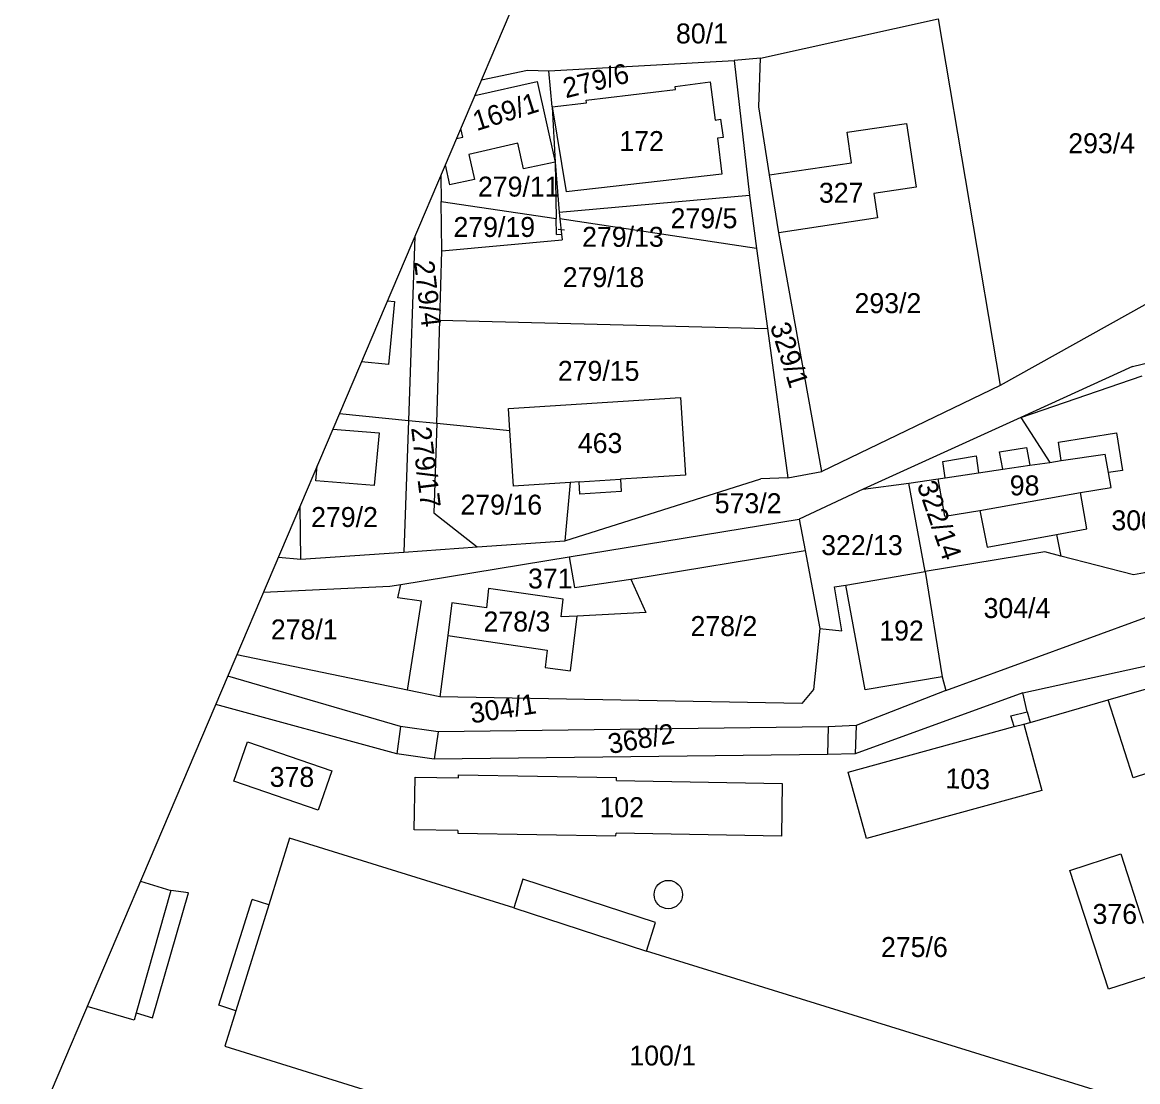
# Model space of a CAD drawing. Extents: x -805826 to -803822, y -1165880 to -1164382.
# Drawn here: x -805826.1 to -805636, y -1165156 to -1164975.4 of the extents above; entities that cross this region are included whole.
import ezdxf

# ---------------------------------------------------------------- set-up
doc = ezdxf.new("R2010")
doc.units = 0
for name, color, linetype in [('formát', 7, 'Continuous'), ('kn_celek - Cisla parcel pomocna', 7, 'Continuous'), ('kn_celek - Cisla pozemkovych parcel', 7, 'Continuous'), ('kn_celek - Cisla stavebnich parcel', 7, 'Continuous'), ('kn_celek - Hranice parcel', 7, 'Continuous'), ('kn_celek - Vnitrni kresby', 7, 'Continuous')]:
    doc.layers.add(name, color=color, linetype=linetype)

msp = doc.modelspace()

# ---------------------------------------------------------------- linework, layer by layer
at = {"layer": 'formát'}
msp.add_line((-805491.17, -1164382.07), (-805826.05, -1165169.15), dxfattribs=at)
at = {"layer": 'kn_celek - Cisla parcel pomocna'}
msp.add_line((-805734.72, -1165010.67), (-805733.68, -1165010.82), dxfattribs=at)
at = {"layer": 'kn_celek - Hranice parcel'}
for p, q in [((-805700.29, -1164981.54), (-805670.01, -1164974.84)), ((-805670.01, -1164974.84), (-805659.45, -1165037.34)), ((-805736.31, -1164983.71), (-805704.74, -1164981.97)), ((-805700.29, -1164981.54), (-805704.74, -1164981.97)), ((-805704.74, -1164981.97), (-805702.16, -1165004.93)), ((-805700.55, -1164989.86), (-805700.29, -1164981.54)), ((-805747.81, -1164985.25), (-805739.97, -1164983.61)), ((-805739.97, -1164983.61), (-805736.31, -1164983.71)), ((-805735.79, -1164989.87), (-805736.31, -1164983.71)), ((-805714.82, -1164986.37), (-805708.85, -1164985.57)), ((-805708.85, -1164985.57), (-805708.01, -1164992.11)), ((-805729.96, -1164988.69), (-805714.77, -1164986.9)), ((-805714.77, -1164986.9), (-805714.82, -1164986.37)), ((-805735.79, -1164989.87), (-805729.91, -1164989.17)), ((-805735.79, -1164989.87), (-805735.26, -1164999.29)), ((-805735.79, -1164989.87), (-805733.38, -1165004.33)), ((-805729.91, -1164989.17), (-805729.96, -1164988.69)), ((-805698.74, -1165001.45), (-805700.55, -1164989.86)), ((-805708.01, -1164992.11), (-805707.08, -1164991.97)), ((-805707.08, -1164991.97), (-805706.65, -1164995.08)), ((-805750.99, -1164995.04), (-805751.33, -1164993.54)), ((-805685.51, -1164994.16), (-805675.37, -1164992.66)), ((-805675.37, -1164992.66), (-805673.76, -1165003.53)), ((-805752.07, -1164995.27), (-805750.99, -1164995.04)), ((-805706.65, -1164995.08), (-805707.62, -1164995.21)), ((-805707.62, -1164995.21), (-805706.85, -1165001.33)), ((-805684.74, -1164999.37), (-805685.51, -1164994.16)), ((-805741.61, -1164996.06), (-805749.94, -1164997.96)), ((-805740.65, -1165000.43), (-805741.61, -1164996.06)), ((-805749.94, -1164997.96), (-805749.02, -1165002.22)), ((-805735.26, -1164999.29), (-805740.65, -1165000.43)), ((-805735.26, -1164999.29), (-805734.57, -1165007.88)), ((-805735.26, -1164999.29), (-805735.06, -1165008.87)), ((-805698.74, -1165001.45), (-805684.74, -1164999.37)), ((-805753.98, -1164999.75), (-805753.25, -1165003.12)), ((-805706.85, -1165001.33), (-805733.38, -1165004.33)), ((-805697.14, -1165011.3), (-805698.74, -1165001.45)), ((-805754.74, -1165001.55), (-805754.68, -1165005.95)), ((-805749.02, -1165002.22), (-805753.25, -1165003.12)), ((-805702.16, -1165004.93), (-805734.57, -1165007.88)), ((-805702.16, -1165004.93), (-805700.92, -1165013.97)), ((-805673.76, -1165003.53), (-805680.97, -1165004.6)), ((-805680.97, -1165004.6), (-805680.35, -1165008.76)), ((-805754.68, -1165005.95), (-805735.06, -1165008.87)), ((-805754.57, -1165014.37), (-805754.68, -1165005.95)), ((-805735, -1165011.63), (-805735.06, -1165008.87)), ((-805734.57, -1165007.88), (-805734.46, -1165008.95)), ((-805700.92, -1165013.97), (-805734.46, -1165008.95)), ((-805734.46, -1165008.95), (-805734.2, -1165011.52)), ((-805680.35, -1165008.76), (-805697.14, -1165011.3)), ((-805759.16, -1165011.94), (-805760.25, -1165043.29)), ((-805754.57, -1165014.37), (-805734.07, -1165012.52)), ((-805735, -1165011.63), (-805734.2, -1165011.52)), ((-805734.2, -1165011.52), (-805734.07, -1165012.52)), ((-805689.79, -1165051.98), (-805697.14, -1165011.3)), ((-805754.9, -1165026.2), (-805754.57, -1165014.37)), ((-805700.92, -1165013.97), (-805699.06, -1165027.61)), ((-805763.83, -1165022.92), (-805762.62, -1165023.04)), ((-805762.62, -1165023.04), (-805763.68, -1165033.73)), ((-805634.8, -1165023.61), (-805659.45, -1165037.34)), ((-805755.4, -1165043.76), (-805754.9, -1165026.2)), ((-805754.9, -1165026.2), (-805699.06, -1165027.61)), ((-805699.06, -1165027.61), (-805695.6, -1165053.06)), ((-805636.9, -1165034.1), (-805627.65, -1165031.81)), ((-805763.68, -1165033.73), (-805768.24, -1165033.28)), ((-805636.9, -1165034.1), (-805655.88, -1165042.77)), ((-805659.45, -1165037.34), (-805689.79, -1165051.98)), ((-805655.88, -1165042.77), (-805635.21, -1165035.71)), ((-805743.19, -1165041.27), (-805713.9, -1165039.4)), ((-805713.9, -1165039.4), (-805713.06, -1165052.59)), ((-805742.95, -1165045), (-805743.19, -1165041.27)), ((-805772.01, -1165042.13), (-805760.25, -1165043.29)), ((-805760.25, -1165043.29), (-805761.05, -1165065.72)), ((-805760.25, -1165043.29), (-805755.4, -1165043.76)), ((-805655.88, -1165042.77), (-805682.75, -1165055.03)), ((-805655.88, -1165042.77), (-805650.95, -1165050.44)), ((-805773.13, -1165044.77), (-805765.26, -1165045.41)), ((-805755.4, -1165043.76), (-805755.92, -1165059.03)), ((-805755.4, -1165043.76), (-805742.95, -1165045)), ((-805742.35, -1165054.47), (-805742.95, -1165045)), ((-805765.26, -1165045.41), (-805766.1, -1165054.37)), ((-805649.5, -1165046.97), (-805639.58, -1165045.39)), ((-805649.03, -1165050.14), (-805649.5, -1165046.97)), ((-805639.58, -1165045.39), (-805638.56, -1165051.81)), ((-805650.95, -1165050.44), (-805649.03, -1165050.14)), ((-805776.02, -1165053.57), (-805775.79, -1165051.03)), ((-805713.06, -1165052.59), (-805724.1, -1165053.29)), ((-805695.6, -1165053.06), (-805689.79, -1165051.98)), ((-805638.56, -1165051.81), (-805640.99, -1165052.14)), ((-805640.52, -1165054.71), (-805640.99, -1165052.14)), ((-805766.1, -1165054.37), (-805776.02, -1165053.57)), ((-805732.68, -1165053.85), (-805742.35, -1165054.47)), ((-805733.6, -1165063.82), (-805700.21, -1165053.24)), ((-805732.68, -1165053.85), (-805733.6, -1165063.82)), ((-805731.19, -1165053.76), (-805732.68, -1165053.85)), ((-805731.05, -1165055.86), (-805731.19, -1165053.76)), ((-805724.1, -1165053.29), (-805723.98, -1165055.4)), ((-805695.6, -1165053.06), (-805700.21, -1165053.24)), ((-805682.75, -1165055.03), (-805675.01, -1165054)), ((-805675.01, -1165054), (-805669.97, -1165053.24)), ((-805672.19, -1165069.06), (-805675.01, -1165054)), ((-805668.85, -1165059.59), (-805669.97, -1165053.24)), ((-805645.74, -1165055.59), (-805640.52, -1165054.71)), ((-805723.98, -1165055.4), (-805731.05, -1165055.86)), ((-805682.75, -1165055.03), (-805693.65, -1165060.13)), ((-805644.66, -1165061.78), (-805645.74, -1165055.59)), ((-805778.62, -1165066.92), (-805778.73, -1165057.92)), ((-805755.92, -1165059.03), (-805748.56, -1165064.85)), ((-805732.89, -1165066.54), (-805693.65, -1165060.13)), ((-805693.65, -1165060.13), (-805692.65, -1165065.44)), ((-805668.85, -1165059.59), (-805662.87, -1165058.63)), ((-805662.87, -1165058.63), (-805661.62, -1165064.89)), ((-805649.83, -1165062.72), (-805644.66, -1165061.78)), ((-805748.56, -1165064.85), (-805733.6, -1165063.82)), ((-805661.62, -1165064.89), (-805649.83, -1165062.72)), ((-805649.83, -1165062.72), (-805649.1, -1165066.4)), ((-805778.62, -1165066.92), (-805761.05, -1165065.72)), ((-805761.05, -1165065.72), (-805748.56, -1165064.85)), ((-805692.65, -1165065.44), (-805690.16, -1165078.72)), ((-805651.79, -1165065.68), (-805672.19, -1165069.06)), ((-805649.1, -1165066.4), (-805651.79, -1165065.68)), ((-805782.42, -1165066.59), (-805778.62, -1165066.92)), ((-805761.57, -1165071.25), (-805732.89, -1165066.54)), ((-805732.89, -1165066.54), (-805731.96, -1165071.77)), ((-805636.7, -1165069.59), (-805649.1, -1165066.4)), ((-805627.18, -1165067.88), (-805636.7, -1165069.59)), ((-805685.74, -1165071.35), (-805672.19, -1165069.06)), ((-805672.19, -1165069.06), (-805669.28, -1165086.99)), ((-805784.95, -1165072.55), (-805763.42, -1165071.55)), ((-805763.42, -1165071.55), (-805761.57, -1165071.25)), ((-805762.09, -1165073.5), (-805761.57, -1165071.25)), ((-805731.96, -1165071.77), (-805722.34, -1165070.32)), ((-805722.34, -1165070.32), (-805719.79, -1165076.04)), ((-805687.66, -1165071.66), (-805685.74, -1165071.35)), ((-805686.4, -1165079.14), (-805687.66, -1165071.66)), ((-805682.44, -1165089.18), (-805685.74, -1165071.35)), ((-805668.7, -1165089.31), (-805617.65, -1165070.65)), ((-805758.03, -1165074.08), (-805762.09, -1165073.5)), ((-805746.63, -1165071.92), (-805746.98, -1165075.23)), ((-805733.9, -1165073.77), (-805746.63, -1165071.92)), ((-805760.44, -1165089.25), (-805758.03, -1165074.08)), ((-805752.85, -1165074.39), (-805753.57, -1165079.93)), ((-805746.98, -1165075.23), (-805752.85, -1165074.39)), ((-805734.25, -1165076.76), (-805733.9, -1165073.77)), ((-805731.5, -1165076.62), (-805734.25, -1165076.76)), ((-805732.62, -1165085.98), (-805731.5, -1165076.62)), ((-805719.79, -1165076.04), (-805731.5, -1165076.62)), ((-805690.16, -1165078.72), (-805691.24, -1165089.16)), ((-805690.16, -1165078.72), (-805686.4, -1165079.14)), ((-805753.57, -1165079.93), (-805754.93, -1165090.38)), ((-805753.57, -1165079.93), (-805736.64, -1165082.43)), ((-805736.64, -1165082.43), (-805736.94, -1165085.42)), ((-805760.44, -1165089.25), (-805789.51, -1165083.26)), ((-805655.57, -1165089.73), (-805629.3, -1165083.94)), ((-805761.61, -1165095.42), (-805791.03, -1165086.85)), ((-805736.94, -1165085.42), (-805732.62, -1165085.98)), ((-805669.28, -1165086.99), (-805682.44, -1165089.18)), ((-805669.28, -1165086.99), (-805668.7, -1165089.31)), ((-805641.01, -1165090.89), (-805628.85, -1165087.41)), ((-805754.93, -1165090.38), (-805760.44, -1165089.25)), ((-805693.23, -1165091.53), (-805754.93, -1165090.38)), ((-805691.24, -1165089.16), (-805693.23, -1165091.53)), ((-805655.57, -1165089.73), (-805684.16, -1165100.09)), ((-805668.7, -1165089.31), (-805683.99, -1165095.25)), ((-805654.8, -1165092.96), (-805655.57, -1165089.73)), ((-805762.23, -1165100.08), (-805793.1, -1165091.71)), ((-805654.3, -1165094.74), (-805641.01, -1165090.89)), ((-805636.77, -1165104.19), (-805641.01, -1165090.89)), ((-805657.58, -1165093.65), (-805654.8, -1165092.96)), ((-805657.05, -1165095.47), (-805657.58, -1165093.65)), ((-805654.8, -1165092.96), (-805654.3, -1165094.74)), ((-805755.2, -1165096.37), (-805761.61, -1165095.42)), ((-805688.76, -1165095.5), (-805755.2, -1165096.37)), ((-805683.99, -1165095.25), (-805688.76, -1165095.5)), ((-805685.34, -1165103.24), (-805657.05, -1165095.47)), ((-805655.38, -1165095.03), (-805654.3, -1165094.74)), ((-805655.38, -1165095.03), (-805652.3, -1165106.33)), ((-805790.02, -1165104.77), (-805787.7, -1165098.04)), ((-805787.7, -1165098.04), (-805773.31, -1165103)), ((-805755.85, -1165100.99), (-805762.23, -1165100.08)), ((-805688.86, -1165100.22), (-805755.85, -1165100.99)), ((-805684.16, -1165100.09), (-805688.86, -1165100.22)), ((-805629.15, -1165101.74), (-805636.77, -1165104.19)), ((-805773.31, -1165103), (-805775.63, -1165109.73)), ((-805759.28, -1165113.07), (-805759.13, -1165104.08)), ((-805759.13, -1165104.08), (-805751.75, -1165104.2)), ((-805751.75, -1165104.2), (-805751.75, -1165103.69)), ((-805751.75, -1165103.69), (-805724.83, -1165104.13)), ((-805682.23, -1165114.53), (-805685.34, -1165103.24)), ((-805775.63, -1165109.73), (-805790.02, -1165104.77)), ((-805724.83, -1165104.64), (-805724.83, -1165104.13)), ((-805724.83, -1165104.64), (-805696.57, -1165105.17)), ((-805696.57, -1165105.17), (-805696.66, -1165114.13)), ((-805652.3, -1165106.33), (-805682.23, -1165114.53)), ((-805751.84, -1165113.2), (-805759.28, -1165113.07)), ((-805751.84, -1165113.2), (-805751.85, -1165113.64)), ((-805780.55, -1165114.5), (-805784.02, -1165125.85)), ((-805742.28, -1165126.36), (-805780.55, -1165114.5)), ((-805751.85, -1165113.64), (-805724.89, -1165114.06)), ((-805724.89, -1165114.06), (-805724.88, -1165113.65)), ((-805696.66, -1165114.13), (-805724.88, -1165113.65)), ((-805647.53, -1165120), (-805638.87, -1165117.13)), ((-805638.87, -1165117.13), (-805635.04, -1165128.95)), ((-805640.97, -1165140.23), (-805647.53, -1165120)), ((-805805.91, -1165121.81), (-805800.74, -1165123.4)), ((-805740.78, -1165121.49), (-805742.28, -1165126.36)), ((-805718.18, -1165128.87), (-805740.78, -1165121.49)), ((-805803.84, -1165145.09), (-805797.75, -1165123.79)), ((-805797.75, -1165123.79), (-805800.74, -1165123.4)), ((-805792.54, -1165142.96), (-805786.88, -1165124.92)), ((-805784.02, -1165125.85), (-805786.88, -1165124.92)), ((-805719.7, -1165133.74), (-805718.18, -1165128.87)), ((-805642.84, -1165157.55), (-805719.7, -1165133.74)), ((-805632.28, -1165137.44), (-805640.97, -1165140.23)), ((-805807.01, -1165145.52), (-805814.98, -1165143.14)), ((-805789.69, -1165143.9), (-805792.54, -1165142.96)), ((-805789.69, -1165143.9), (-805791.54, -1165149.95)), ((-805806.67, -1165144.22), (-805807.01, -1165145.52)), ((-805806.67, -1165144.22), (-805803.84, -1165145.09)), ((-805791.54, -1165149.95), (-805688.4, -1165181.93))]:
    msp.add_line(p, q, dxfattribs=at)
at = {"layer": 'kn_celek - Vnitrni kresby'}
for p, q in [((-805748.95, -1164987.94), (-805738.3, -1164985.51)), ((-805738.3, -1164985.51), (-805735.26, -1164999.29)), ((-805659.52, -1165048.65), (-805654.95, -1165047.88)), ((-805658.97, -1165051.61), (-805659.52, -1165048.65)), ((-805654.95, -1165047.88), (-805654.39, -1165050.93)), ((-805669.2, -1165050.26), (-805663.51, -1165049.32)), ((-805668.82, -1165053.08), (-805669.2, -1165050.26)), ((-805663.51, -1165049.32), (-805663.1, -1165052.23)), ((-805654.39, -1165050.93), (-805650.95, -1165050.44)), ((-805649.03, -1165050.14), (-805641.54, -1165049.03)), ((-805640.99, -1165052.14), (-805641.54, -1165049.03)), ((-805668.82, -1165053.08), (-805663.1, -1165052.23)), ((-805663.1, -1165052.23), (-805658.97, -1165051.61)), ((-805658.97, -1165051.61), (-805654.39, -1165050.93)), ((-805731.19, -1165053.76), (-805724.1, -1165053.29)), ((-805669.97, -1165053.24), (-805668.82, -1165053.08)), ((-805662.87, -1165058.63), (-805645.74, -1165055.59)), ((-805722.34, -1165070.32), (-805692.65, -1165065.44)), ((-805761.61, -1165095.42), (-805762.23, -1165100.08)), ((-805755.2, -1165096.37), (-805755.85, -1165100.99)), ((-805688.76, -1165095.5), (-805688.86, -1165100.22)), ((-805683.99, -1165095.25), (-805684.16, -1165100.09)), ((-805657.05, -1165095.47), (-805655.38, -1165095.03)), ((-805800.74, -1165123.4), (-805806.67, -1165144.22)), ((-805784.02, -1165125.85), (-805789.69, -1165143.9)), ((-805742.28, -1165126.36), (-805719.7, -1165133.74))]:
    msp.add_line(p, q, dxfattribs=at)
msp.add_circle((-805715.98, -1165124.09), 2.42, dxfattribs=at)

# ---------------------------------------------------------------- texts
at = {"layer": 'kn_celek - Cisla parcel pomocna'}
for s, p in [('80/1', (-805714.67, -1164979.04)), ('279/13', (-805730.66, -1165013.7)), ('573/2', (-805708.06, -1165059.1))]:
    msp.add_text(s, height=3.4, dxfattribs=at).set_placement(p)
at = {"layer": 'kn_celek - Cisla pozemkovych parcel'}
for s, rotation, p in [('279/6', 14.04, (-805733.44, -1164988.4)), ('279/4', 276.624, (-805759.3, -1165016.23)), ('329/1', 287.685, (-805698.68, -1165027.18)), ('279/17', 277.083, (-805759.81, -1165044.56)), ('322/14', 289.116, (-805673.66, -1165054.25)), ('304/1', 8.937, (-805749.5, -1165094.94)), ('368/2', 9.684, (-805725.94, -1165100.14))]:
    msp.add_text(s, height=3.4, rotation=rotation, dxfattribs=at).set_placement(p)
for s, height, p in [('293/4', 3.4, (-805647.82, -1164997.75)), ('279/11', 3.4, (-805748.41, -1165005.14)), ('279/5', 3.4, (-805715.58, -1165010.54)), ('279/19', 3.4, (-805752.58, -1165012.02)), ('279/13', 0.005, (-805734.72, -1165010.67)), ('279/18', 3.4, (-805733.97, -1165020.57)), ('293/2', 3.4, (-805684.24, -1165025)), ('279/15', 3.4, (-805734.8, -1165036.54)), ('279/16', 3.4, (-805751.39, -1165059.34)), ('279/2', 3.4, (-805776.84, -1165061.45)), ('300', 3.4, (-805640.47, -1165062.01)), ('322/13', 3.4, (-805689.93, -1165066.24)), ('371', 3.4, (-805739.88, -1165071.93)), ('304/4', 3.4, (-805662.25, -1165076.96)), ('278/1', 3.4, (-805783.7, -1165080.61)), ('278/3', 3.4, (-805747.46, -1165079.26)), ('278/2', 3.4, (-805712.19, -1165080.03)), ('275/6', 3.4, (-805679.73, -1165134.73))]:
    msp.add_text(s, height=height, dxfattribs=at).set_placement(p)
at = {"layer": 'kn_celek - Cisla stavebnich parcel'}
for s, rotation, p in [('169/1', 17.532, (-805748.64, -1164994)), ('103', 358.56, (-805668.77, -1165105.97))]:
    msp.add_text(s, height=3.4, rotation=rotation, dxfattribs=at).set_placement(p)
for s, p in [('172', (-805724.32, -1164997.38)), ('327', (-805690.31, -1165006.19)), ('463', (-805731.39, -1165048.84)), ('98', (-805657.79, -1165056.06)), ('192', (-805680.02, -1165080.8)), ('378', (-805783.9, -1165105.74)), ('102', (-805727.7, -1165110.9)), ('376', (-805643.68, -1165129.09)), ('100/1', (-805722.61, -1165153.22))]:
    msp.add_text(s, height=3.4, dxfattribs=at).set_placement(p)

doc.saveas('drawing.dxf')
